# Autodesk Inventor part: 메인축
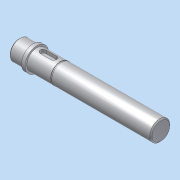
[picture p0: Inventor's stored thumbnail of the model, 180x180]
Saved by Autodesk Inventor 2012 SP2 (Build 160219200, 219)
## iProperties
Company: 한국ATC센터
Created: 2014-12
Part Number: 메인축
Document SubType Name: Modeling
Designer: KYOUNG IL JANG
Density: 1 g/cm^3
Mass: 27.2374 g
Surface Area: 71.2962 cm^2
Volume: 27.2374 cm^3
Material: 기본값
Author: KYOUNG IL JANG
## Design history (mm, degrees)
sketch "스케치1"
  geometry: L1 (0, 0)-(120, 0); L2 (0, 0)-(0, 7.5); L3 (1, 8.5)-(12, 8.5); L4 (12, 8.5)-(12, 10); L5 (12, 10)-(15, 10); L6 (15, 10)-(15, 8.5); L7 (15, 8.5)-(119, 8.5); L8 (120, 0)-(120, 7.5); L9 (1, 8.5)-(0, 7.5); L10 (119, 8.5)-(120, 7.5); 2 further points
  constraints: 20 end point, 4 point on line, 3 parallel, 3 perpendicular, 1 collinear, 1 horizontal
  dimensions: "d0" = 12 distance of point (0, 8.5) L3.end; "d1" = 17 diameter of L3 L1; "d2" = 20 diameter of L5 L1; "d3" = 17 diameter of L7 L1; "d4" = 3 distance of L4.end L5.end; "d5" = 120 distance of L1.start L1.end; "d6" = 1 distance of L3.start point (0, 8.5); "d7" = 1 distance of L2.end point (0, 8.5) (= d6); "d8" = 1 distance of L7.end point (120, 8.5) (= d6); "d9" = 1 distance of L8.end point (120, 8.5) (= d8)
revolve "회전1" sketch "스케치1" stored, may be unused: angle "d10" = 90 deg
node "작업 평면1"
sketch "스케치2"
  geometry: L1 (-46.5, 2.5)-(-37.5, 2.5); L2 (-37.5, -2.5)-(-46.5, -2.5); L3 (-52, -10)-(-52, 10) reference; A1 r 2.5 centre (-37.5, 0) between (-37.5, -2.5) and (-37.5, 2.5); A2 r 2.5 centre (-46.5, 0) between (-46.5, 2.5) and (-46.5, -2.5); 1 further point
  constraints: 4 end point, 4 point on circle, 4 tangent, 2 centre point, 1 horizontal, 1 horizontal alignment, 1 parallel
  dimensions: "d11" = 5 distance between parallel lines of L2 L1; "d12" = 3 distance edge to line of A2 L3; "d13" = 14 dimension on A1 A2
extrude "돌출1" cut sketch "스케치2" distance "d14" = 3; taper "d15" = 0 deg
sketch "스케치3"
  geometry: L1 (15, 8.5)-(119, 8.5) reference; L2 (35, 8.5)-(36.15, 8.5); L3 (36.15, 8.5)-(36.15, 8.1); L4 (36.15, 8.1)-(35, 8.1); L5 (35, 8.1)-(35, 8.5); L6 (15, -10)-(15, 10) reference; L7 (-23.8, 0)-(142.8, 0) reference; 1 further point
  constraints: 8 end point, 2 parallel, 1 horizontal, 1 perpendicular, 1 point on line
  dimensions: "d16" = 1.15 distance of L3.end L4.end; "d17" = 20 distance between parallel lines of L5 L6; "d18" = 8.1 distance from line of L4 point (0, 0)
revolve "회전2" sketch "스케치3" stored, may be unused: angle "d19" = 90 deg
node "솔리드1"
